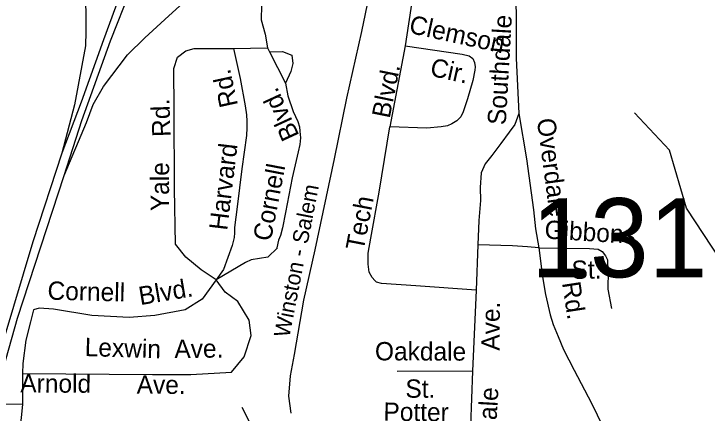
# Model space of a CAD drawing. Extents: x 1547597 to 1699558, y 810033 to 920809.
# Drawn here: x 1633767 to 1637363, y 836281 to 838352 of the extents above; entities that cross this region are included whole.
import ezdxf

# ---------------------------------------------------------------- set-up
doc = ezdxf.new("R2010")
doc.units = 0
for name, color, linetype in [('Exist Hydrographic Creek Single Shore', 7, 'Continuous'), ('Exist Railroad Mainline', 7, 'Continuous'), ('Exist Railroad Mainline Label', 7, 'Continuous'), ('Exist Road Non-System Type 51', 7, 'Continuous'), ('Exist Road Non-System Type 51 Label', 7, 'Continuous'), ('Exist Road Primary US Divided Attributed', 7, 'Continuous'), ('Exist Road Primary US Ramp 1 Lane  Attributed', 7, 'Continuous'), ('Exist Road Secondary Structure Standard Bridge Number Label', 7, 'Continuous')]:
    doc.layers.add(name, color=color, linetype=linetype)

msp = doc.modelspace()

# ---------------------------------------------------------------- linework, layer by layer
at = {"layer": 'Exist Hydrographic Creek Single Shore'}
for points in [[(1639978, 832883.6), (1639649, 833221.8), (1639558.9, 833407.4), (1639497.9, 833822.3), (1639391.9, 834034.6), (1639128.9, 834387.8), (1638614, 835251.7), (1638408.9, 835538.2), (1638123, 836016.7), (1637835, 836311.4), (1637746, 836497.1), (1637697.9, 836672), (1637255, 837344.1), (1637166.9, 837644.6), (1636985.9, 837838.7)], [(1635649.9, 834852.3), (1635519.9, 835170.1), (1635249.9, 835576.1), (1635096.9, 836025.6), (1634950.9, 836310.9)]]:
    msp.add_lwpolyline(points, dxfattribs=at)
at = {"layer": 'Exist Railroad Mainline'}
msp.add_lwpolyline([(1635205.3, 836280.2), (1635192.5, 836368.5), (1635201.3, 836473.6), (1635222.8, 836585.3), (1635271.3, 836866.5), (1635329.2, 837128.7), (1635429.6, 837599.9), (1635493.6, 837913.9), (1635570.8, 838259.8), (1635609.2, 838445.3), (1635627.5, 838563.4), (1635699.9, 838980), (1635769.8, 839278.1), (1635820.3, 839595.8), (1635881.7, 839869.1), (1635919.3, 840057.7)], dxfattribs=at)
at = {"layer": 'Exist Road Non-System Type 51'}
for p, q in [((1635856.2, 838578.5), (1635796.2, 838185.7)), ((1635796.2, 838185.7), (1635716.2, 837765.4)), ((1636172.5, 837154.4), (1636165, 836918.3))]:
    msp.add_line(p, q, dxfattribs=at)
for points in [[(1636345.8, 838703.8), (1636370.1, 838630.8), (1636372.3, 838122.7), (1636385.5, 837835.5)], [(1635056.1, 838541.4), (1635054.2, 838478.5), (1635050.5, 838397.1), (1635048.7, 838321.2), (1635070.9, 838247.2), (1635082, 838175)], [(1634816.3, 836972.1), (1634739, 837023.7), (1634659.2, 837089.4), (1634605.3, 837157.5), (1634600.6, 837443.8), (1634598.2, 837855.1), (1634595.9, 838068.7), (1634614.7, 838127.4), (1634659.2, 838160.2), (1634701.4, 838172), (1634774.1, 838172), (1634906.6, 838172.3)], [(1634906.6, 838172.3), (1634941.2, 838015.9), (1634966.8, 837875.3), (1634973.6, 837827.7), (1634975.4, 837795.7), (1634975.7, 837760.9), (1634972.7, 837721.7), (1634949.1, 837547.9), (1634925.3, 837350.3), (1634910.5, 837244.3), (1634910.2, 837216), (1634910.1, 837192), (1634898.4, 837150.4), (1634853.9, 837026.1), (1634816.3, 836972.1)], [(1634906.6, 838172.3), (1635082, 838175)], [(1635082, 838175), (1635093.1, 838154.7)], [(1635796.2, 838185.7), (1636091.8, 838142), (1636127.6, 838133.9), (1636147.6, 838119.7), (1636155.4, 838099.5), (1636159.1, 838077.6), (1636157, 838059.6), (1636146.7, 838005.6), (1636119.7, 837911.9), (1636097.2, 837844.1), (1636085, 837818.2), (1636064.8, 837796.4), (1636038.6, 837780.7), (1636016.6, 837770.7), (1635982.5, 837765), (1635908.5, 837759.7), (1635716.2, 837765.4)], [(1635093.1, 838154.7), (1635174.9, 837991.9)], [(1635094.9, 838154.7), (1635159.6, 838156.5), (1635207.7, 838138), (1635213.3, 838093.6), (1635204, 838052.9), (1635174.9, 837991.9)], [(1635174.9, 837991.9), (1635187.6, 837926.9), (1635214.7, 837844.6), (1635239.3, 837794), (1635248.3, 837765.9), (1635250.6, 837743.6), (1635254.1, 837708.7), (1635249.8, 837674.6), (1635241.9, 837635.9), (1635210.9, 837500.5), (1635176.4, 837322.1), (1635159.8, 837242.3), (1635149.4, 837201.4), (1635139.3, 837177.6), (1635130.6, 837139), (1635133.5, 837138.5), (1635084, 837089.7), (1634997, 837076.7), (1634967.5, 837062.5), (1634816.3, 836972.1)], [(1636385.5, 837835.5), (1636365.7, 837778), (1636336.4, 837737.5), (1636292.4, 837679.8), (1636245.4, 837617.5), (1636210.5, 837573.5), (1636190.7, 837526.4), (1636184.7, 837450.5), (1636186.2, 837383.7), (1636178.6, 837280.4), (1636172.5, 837154.4)], [(1636385.5, 837835.5), (1636426, 837599.3), (1636462.4, 837335.1), (1636473, 837236.4), (1636489.7, 837137.7)], [(1636165, 836918.3), (1635851.5, 836940.4), (1635673.7, 836953.9), (1635647.6, 836960.2), (1635639.7, 836968.1), (1635625.8, 836984.2), (1635608.7, 837011.3), (1635603.7, 837053.8), (1635603.7, 837111.4), (1635618.7, 837188.9), (1635661.2, 837426.6), (1635716.2, 837765.4)], [(1636489.7, 837137.7), (1636430.5, 837143.8), (1636353.1, 837148.3), (1636172.5, 837154.4)], [(1636489.7, 837137.7), (1636752.9, 837135), (1636797, 837131.2), (1636818.4, 837119.8), (1636836, 837095.9), (1636846.1, 837075.7), (1636846.1, 837054.3), (1636848.6, 837020.3), (1636847.3, 836923.3), (1636865.8, 836823.8)], [(1636489.7, 837137.7), (1636508.7, 836987.6), (1636523.8, 836895.6), (1636549, 836791.1), (1636564.1, 836740.7), (1636590.5, 836678.5), (1636618.2, 836610.4), (1636672.3, 836504.6), (1636762.3, 836333.3), (1636850.5, 836151.9), (1636933.5, 835972.6), (1636978.9, 835859.2), (1636988.9, 835826.5), (1637004, 835771), (1637014.1, 835710.6), (1637039.3, 835619.9)], [(1633810.8, 836485.6), (1634485.7, 836481.6), (1634685, 836481.6), (1634896.1, 836493.4), (1634961.7, 836573.1), (1634996.9, 836683.4), (1634987.5, 836763.2), (1634928.9, 836859.4), (1634863.2, 836908.7), (1634816.3, 836972.1)], [(1634816.3, 836972.1), (1634743.8, 836871.4), (1634654.7, 836817.4), (1634497.5, 836786.9), (1634363.9, 836777.5), (1634171.6, 836786.9), (1633972.3, 836819.8), (1633897.2, 836824.5), (1633869.1, 836817.4), (1633852.4, 836753.6), (1633828.8, 836659.6), (1633813, 836538.7), (1633810.8, 836485.6)], [(1636165, 836918.3), (1636144.7, 836499.2)], [(1633810.8, 836485.6), (1633810.8, 836325.6)], [(1636144.7, 836499.2), (1635754.8, 836496.2)], [(1636144.7, 836499.2), (1636135.6, 836215.8)], [(1633810.8, 836325.6), (1633105.3, 836335.4)], [(1633810.8, 836325.6), (1633797.8, 836190.1), (1633795.5, 835920.2), (1633797.5, 835716.1)]]:
    msp.add_lwpolyline(points, dxfattribs=at)
at = {"layer": 'Exist Road Primary US Divided Attributed'}
for points in [[(1634355.9, 838557), (1634231.3, 838216.7), (1634116.6, 837893.2), (1634015.1, 837629.5)], [(1634027, 837513.2), (1634118.4, 837798.8), (1634268.5, 838211.9), (1634304.1, 838304.1), (1634402.2, 838554.1)], [(1634015.1, 837629.5), (1633864.3, 837169.1), (1633612.1, 836331.7), (1633570.3, 836185.2)], [(1633619.2, 836189.6), (1633785.9, 836773.6), (1634027, 837513.2)]]:
    msp.add_lwpolyline(points, dxfattribs=at)
at = {"layer": 'Exist Road Primary US Ramp 1 Lane  Attributed'}
for points in [[(1634122.9, 838564.7), (1634135.5, 838476.5), (1634139.5, 838361.6), (1634140.7, 838260.8), (1634138.8, 838185.3), (1634081, 837880.1), (1634015.1, 837629.5)], [(1634027, 837513.2), (1634142.7, 837788.7), (1634178.4, 837882.3), (1634231.2, 837974.9), (1634355.6, 838140), (1634446.2, 838226.9), (1634550, 838323.2), (1634665.1, 838429), (1634687.2, 838461.8), (1634696.7, 838502.3), (1634698.4, 838529.8), (1634694.1, 838547.1)]]:
    msp.add_lwpolyline(points, dxfattribs=at)

# ---------------------------------------------------------------- texts
at = {"layer": 'Exist Railroad Mainline Label'}
msp.add_text('Winston - Salem', height=82.021, rotation=78.9461, dxfattribs=at).set_placement((1635195.1, 836669.2))
at = {"layer": 'Exist Road Non-System Type 51 Label'}
for s, rotation, p in [('Clemson', 347.633, (1635811.6, 838253.8)), ('Southdale', 86.7901, (1636318, 837773.3)), ('Cir.', 347.633, (1635920.6, 838031.9)), ('Rd.', 102.2793, (1634929.5, 837878.2)), ('Blvd.', 78.6099, (1635715.6, 837806.1)), ('Blvd.', 114.7778, (1635248.9, 837721)), ('Rd.', 91.9103, (1634579.8, 837715.2)), ('Overdale', 277.5637, (1636479.2, 837804.7)), ('Harvard', 83.1255, (1634872.9, 837225.7)), ('Yale', 89.744, (1634570.9, 837328)), ('Cornell', 79.1155, (1635099.3, 837168.3)), ('Tech', 79.0688, (1635580.3, 837119.6)), ('Gibbons', 356.5352, (1636517.1, 837186.9)), ('St.', 0.9732, (1636659.9, 836976.6)), ('Blvd.', 9.5557, (1634422.4, 836840.7)), ('Cornell', 358.6067, (1633940.3, 836869.5)), ('Rd.', 278.7522, (1636609.7, 836956.3)), ('Ave.', 89.6111, (1636286, 836604.7)), ('Lexwin', 358.3088, (1634133.1, 836577)), ('Ave.', 0.769, (1634599.7, 836566.1)), ('Oakdale', 359.7962, (1635639.4, 836554.8)), ('Arnold', 359.6592, (1633800, 836388.4)), ('Ave.', 359.6592, (1634403.5, 836381.7)), ('St.', 359.7962, (1635797.4, 836360.9)), ('Southdale', 86.7901, (1636248.2, 835841.4)), ('Potter', 359.5027, (1635683.4, 836241.2))]:
    msp.add_text(s, height=95, rotation=rotation, dxfattribs=at).set_placement(p)
at = {"layer": 'Exist Road Secondary Structure Standard Bridge Number Label'}
msp.add_text('131', height=410.1, dxfattribs=at).set_placement((1636449.4, 836985.6))

doc.saveas('drawing.dxf')
